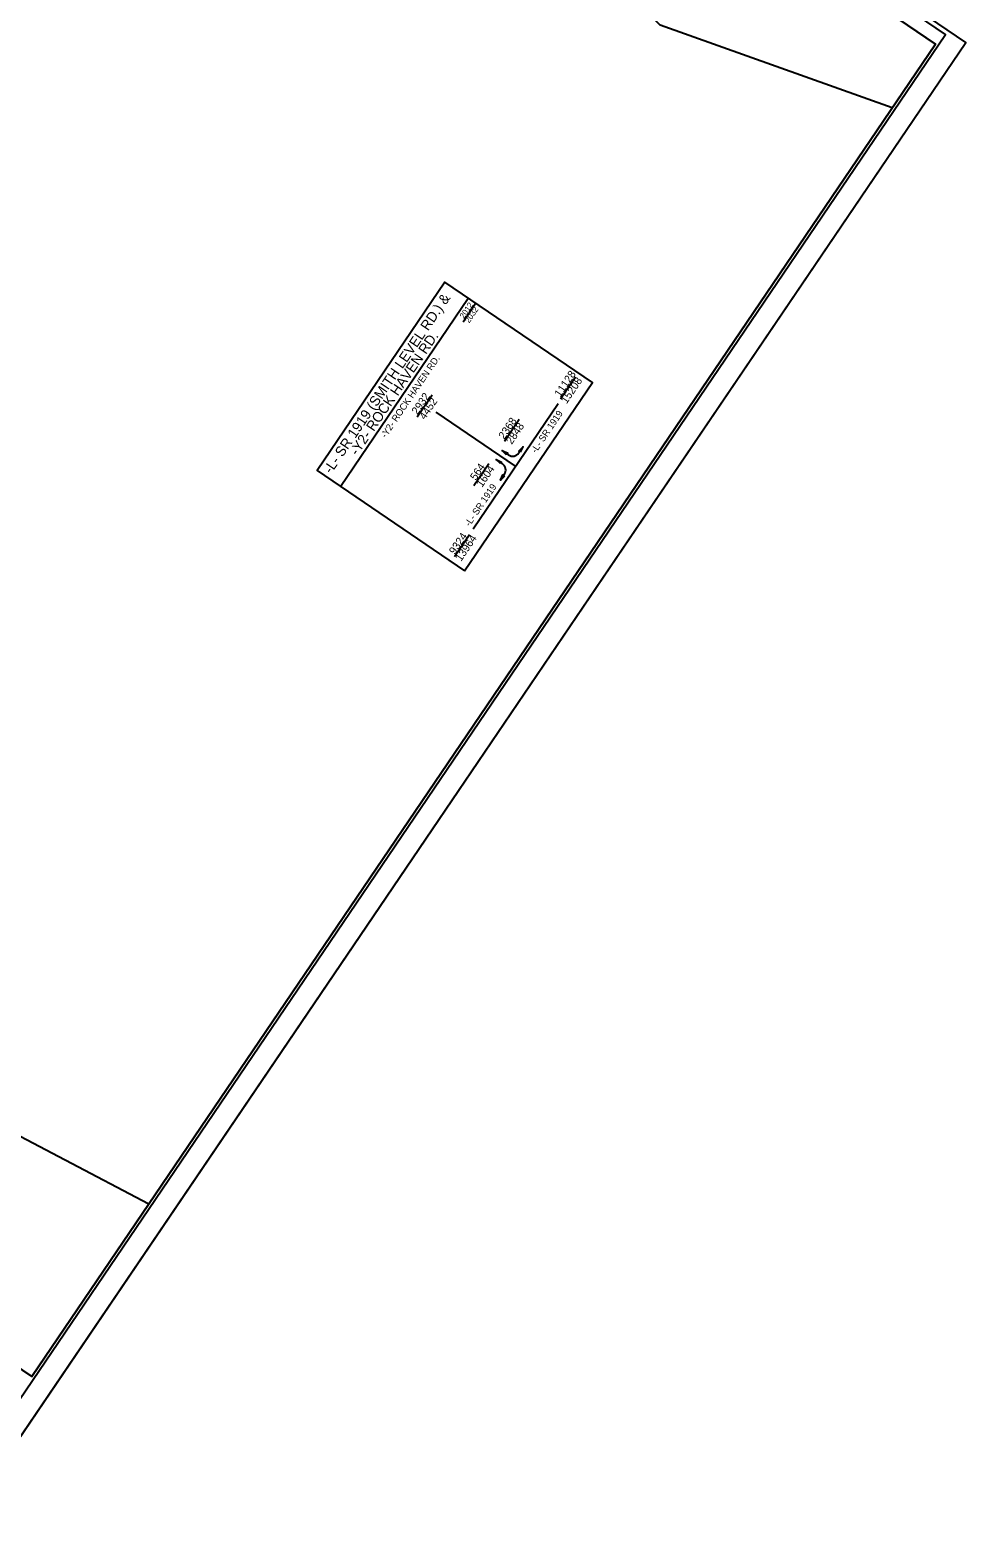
# Model space of a CAD drawing. Extents: x 1975407 to 1977258, y 778272 to 780396.
# Drawn here: x 1976387 to 1977258, y 778272 to 779677 of the extents above; entities that cross this region are included whole.
import ezdxf

# ---------------------------------------------------------------- set-up
doc = ezdxf.new("R2010")
doc.units = 0
for name, color, linetype in [('Prop PHM Label Text', 7, 'Continuous'), ('Prop PHM White Label Box', 7, 'Continuous'), ('Sheet Clip Boundary CELL', 7, 'Continuous'), ('Sheet Cutting Line CELL', 7, 'Continuous'), ('Sheet Plan CELL', 7, 'Continuous'), ('Sheet Plan Layout CELL', 7, 'Continuous'), ('Sheet Plot Border Inside CELL', 7, 'Continuous'), ('Sheet Plot Border Outside CELL', 7, 'Continuous')]:
    doc.layers.add(name, color=color, linetype=linetype)

msp = doc.modelspace()

# ---------------------------------------------------------------- linework, layer by layer
at = {"layer": 'Prop PHM Label Text'}
for p, q in [((1976675.7, 779251.6), (1976794.7, 779426.9)), ((1976790, 779405), (1976801.2, 779421.5)), ((1976880.8, 779333.2), (1976894.7, 779353.7)), ((1976747.4, 779316.4), (1976761.3, 779336.9)), ((1976839, 779270.4), (1976765, 779320.6)), ((1976799.3, 779212), (1976878.6, 779328.8)), ((1976828.5, 779293.7), (1976842.4, 779314.2)), ((1976845.9, 779288.4), (1976842.1, 779282.8)), ((1976826.7, 779272.6), (1976820.9, 779276.6)), ((1976832.4, 779280.9), (1976826.5, 779284.9)), ((1976800.2, 779252.3), (1976814.1, 779272.8)), ((1976824.8, 779257.3), (1976828.6, 779262.9)), ((1976782.1, 779186.4), (1976796, 779206.9))]:
    msp.add_line(p, q, dxfattribs=at)
for points in [[(1976843.6, 779283.4), (1976845.9, 779288.4), (1976842, 779284.4), (1976843.2, 779284.4)], [(1976824.8, 779272.8), (1976820.9, 779276.6), (1976825.9, 779274.3), (1976824.8, 779273.9)], [(1976830.5, 779281.1), (1976826.5, 779284.9), (1976831.6, 779282.6), (1976830.4, 779282.2)], [(1976828.6, 779261.2), (1976824.8, 779257.3), (1976827.1, 779262.3), (1976827.5, 779261.2)]]:
    msp.add_lwpolyline(points, close=True, dxfattribs=at)
for centre, start, end in [((1976836.3, 779286.7), 235.8441, 325.8441), ((1976822.8, 779266.8), 325.8441, 55.8441)]:
    msp.add_arc(centre, 7, start, end, dxfattribs=at)
at = {"layer": 'Prop PHM White Label Box'}
msp.add_lwpolyline([(1976791.5, 779173), (1976910.5, 779348.4), (1976772.9, 779441.7), (1976654, 779266.4)], close=True, dxfattribs=at)
at = {"layer": 'Sheet Clip Boundary CELL'}
msp.add_lwpolyline([(1976497.2, 778583.1), (1977189.9, 779604.2), (1976973.8, 779681.3), (1976888, 779765.6), (1976619.5, 780027.3), (1976496, 780074.9), (1976389.8, 779918.3), (1976214.8, 780037.1), (1975535, 779035.2), (1975693.9, 778927.3), (1975738.3, 778974.2), (1975853.6, 778922.6), (1976185.1, 778747.3)], close=True, dxfattribs=at)
at = {"layer": 'Sheet Cutting Line CELL'}
msp.add_line((1976313.3, 778272), (1977258.5, 779665.2), dxfattribs=at)
at = {"layer": 'Sheet Plan CELL'}
msp.add_line((1976388.1, 778422.4), (1976388.1, 778422.4), dxfattribs=at)
for points in [[(1976361.4, 780253.3), (1975519.3, 779012), (1976388.1, 778422.4), (1977230.3, 779663.7)], [(1976388.1, 778422.4), (1975519.3, 779011.9), (1976249.1, 780087.7), (1976373.3, 780003.5), (1976485.6, 780169), (1977230.3, 779663.7)]]:
    msp.add_lwpolyline(points, close=True, dxfattribs=at)
at = {"layer": 'Sheet Plan Layout CELL'}
msp.add_lwpolyline([(1975519.3, 779011.9), (1976388.1, 778422.4), (1977230.3, 779663.7), (1976536.4, 780134.5), (1976402.1, 779936.5), (1976227.1, 780055.3)], close=True, dxfattribs=at)
at = {"layer": 'Sheet Plot Border Inside CELL'}
msp.add_lwpolyline([(1976304, 778294), (1977239.4, 779672.7), (1976366.4, 780265), (1975431, 778886.3)], close=True, dxfattribs=at)
at = {"layer": 'Sheet Plot Border Outside CELL'}
msp.add_lwpolyline([(1976313.3, 778272), (1977258.5, 779665.2), (1976352.4, 780279.9), (1975407.2, 778886.8)], close=True, dxfattribs=at)

# ---------------------------------------------------------------- texts
at = {"layer": 'Prop PHM Label Text'}
for s, height, p in [('-L- SR 1919 (SMITH LEVEL RD.) &', 9.414, (1976667.1, 779262.7)), ('2012', 5.4, (1976790.8, 779407.4)), ('2032', 5.4, (1976795.7, 779403.3)), ('-Y2- ROCK HAVEN RD.', 9.414, (1976691.5, 779279.6)), ('-Y2- ROCK HAVEN RD.', 6.276, (1976718, 779296.1)), ('11128', 7.2, (1976880.5, 779334.2)), ('15208', 7.2, (1976886.5, 779328)), ('2932', 7.2, (1976747.5, 779317.9)), ('4452', 7.2, (1976754.5, 779313.2)), ('-L- SR 1919', 6.276, (1976858, 779282.1)), ('2368', 7.2, (1976828.4, 779294.9)), ('2848', 7.2, (1976835.4, 779290.1)), ('564', 7.2, (1976801.9, 779256.6)), ('1604', 7.2, (1976807.8, 779250.2)), ('-L- SR 1919', 6.276, (1976796.2, 779213.8)), ('9324', 7.2, (1976782.3, 779187.6)), ('13964', 7.2, (1976788.2, 779181.2))]:
    msp.add_text(s, height=height, rotation=55.853, dxfattribs=at).set_placement(p)

doc.saveas('drawing.dxf')
